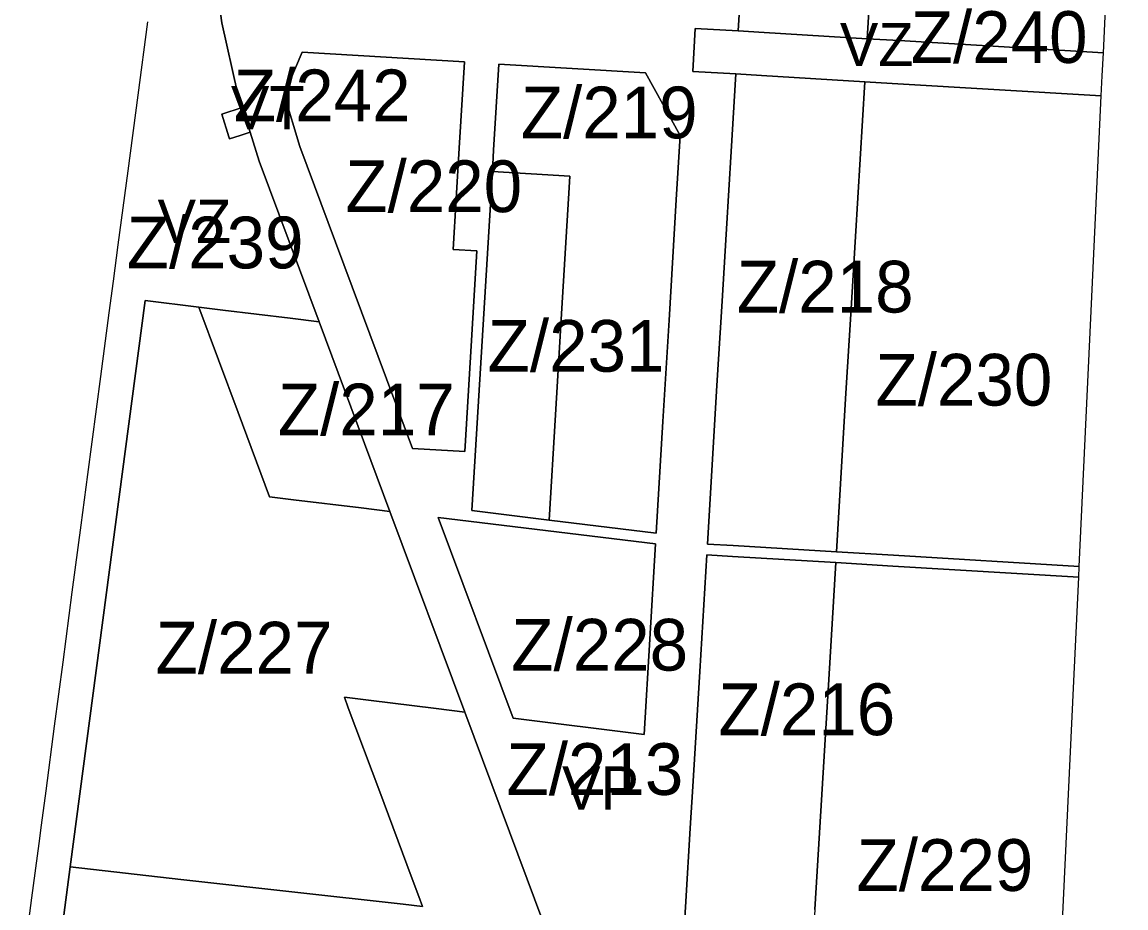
# Model space of a CAD drawing. Extents: x -521939 to -518034, y -1194984 to -1189555.
# Drawn here: x -519472.6 to -519216.4, y -1191421.3 to -1191215.8 of the extents above; entities that cross this region are included whole.
import ezdxf

# ---------------------------------------------------------------- set-up
doc = ezdxf.new("R2010")
doc.units = 0
for name, color, linetype in [('95420023', 7, 'Continuous'), ('96122023', 7, 'Continuous'), ('96202223', 7, 'Continuous'), ('96202323', 7, 'Continuous')]:
    doc.layers.add(name, color=color, linetype=linetype)

msp = doc.modelspace()

# ---------------------------------------------------------------- linework, layer by layer
at = {"layer": '95420023'}
for points in [[(-519269, -1191220.09), (-519221.65, -1191222.94), (-519219.11, -1191168.85), (-519216.44, -1191111.73), (-519216.41, -1191111.11)], [(-519302.94, -1191160.9), (-519304.09, -1191179.86), (-519305.23, -1191198.83), (-519306.37, -1191217.84)], [(-519306.37, -1191217.84), (-519305.23, -1191198.83), (-519304.09, -1191179.86), (-519302.94, -1191160.9)], [(-519274.14, -1191181.66), (-519275.28, -1191200.63), (-519276.43, -1191219.64)], [(-519276.43, -1191219.64), (-519275.28, -1191200.63), (-519274.14, -1191181.66)], [(-519428.47, -1191199.49), (-519426.21, -1191215.98)], [(-519426.21, -1191215.98), (-519428.47, -1191199.49)], [(-519443.51, -1191215.75), (-519445.75, -1191232.74), (-519448.07, -1191250.27), (-519450.34, -1191267.46), (-519451.46, -1191275.9), (-519452.43, -1191283.22), (-519454.38, -1191298), (-519457.39, -1191320.76), (-519458.94, -1191332.49), (-519461, -1191348.01), (-519463.15, -1191364.31), (-519465.11, -1191379.15), (-519467.09, -1191394.09), (-519468.15, -1191402.09), (-519468.71, -1191406.36), (-519470.37, -1191418.91), (-519472.32, -1191433.7), (-519472.58, -1191435.69)], [(-519426.21, -1191215.98), (-519422.56, -1191232.21)], [(-519422.56, -1191232.21), (-519426.21, -1191215.98)], [(-519316.35, -1191217.24), (-519316.95, -1191227.22), (-519306.97, -1191227.82)], [(-519316.95, -1191227.22), (-519316.35, -1191217.24)], [(-519306.37, -1191217.84), (-519316.35, -1191217.24)], [(-519316.35, -1191217.24), (-519306.37, -1191217.84)], [(-519276.43, -1191219.64), (-519300.38, -1191218.2), (-519306.37, -1191217.84)], [(-519306.37, -1191217.84), (-519300.38, -1191218.2), (-519276.43, -1191219.64)], [(-519221.65, -1191222.94), (-519269, -1191220.09), (-519276.43, -1191219.64)], [(-519276.43, -1191219.64), (-519269, -1191220.09)], [(-519371.12, -1191245), (-519369.92, -1191225.04), (-519407.56, -1191222.77), (-519411.75, -1191232.59)], [(-519411.75, -1191232.59), (-519407.56, -1191222.77), (-519369.92, -1191225.04), (-519371.12, -1191245)], [(-519270.66, -1191230.01), (-519222.12, -1191232.93), (-519221.9, -1191228.24), (-519221.65, -1191222.94)], [(-519361.93, -1191225.52), (-519363.14, -1191245.48), (-519363.44, -1191250.47)], [(-519363.44, -1191250.47), (-519363.14, -1191245.48), (-519361.93, -1191225.52)], [(-519327.89, -1191227.57), (-519361.93, -1191225.52)], [(-519361.93, -1191225.52), (-519327.89, -1191227.57)], [(-519319.85, -1191242.08), (-519327.89, -1191227.57)], [(-519327.89, -1191227.57), (-519319.85, -1191242.08)], [(-519310.22, -1191281.73), (-519309.14, -1191263.76), (-519308.05, -1191245.79), (-519306.97, -1191227.82), (-519316.95, -1191227.22)], [(-519306.97, -1191227.82), (-519308.05, -1191245.79), (-519309.14, -1191263.76)], [(-519300.98, -1191228.18), (-519306.97, -1191227.82)], [(-519306.97, -1191227.82), (-519300.98, -1191228.18), (-519277.03, -1191229.63)], [(-519277.03, -1191229.63), (-519300.98, -1191228.18)], [(-519278.11, -1191247.59), (-519277.03, -1191229.63)], [(-519277.03, -1191229.63), (-519278.11, -1191247.59)], [(-519270.66, -1191230.01), (-519277.03, -1191229.63)], [(-519277.03, -1191229.63), (-519270.66, -1191230.01)], [(-519227.23, -1191342.07), (-519227.23, -1191342.05), (-519224.53, -1191284.5), (-519222.12, -1191232.93), (-519270.66, -1191230.01)], [(-519422.56, -1191232.21), (-519421.48, -1191235.61)], [(-519421.48, -1191235.61), (-519422.56, -1191232.21)], [(-519411.75, -1191232.59), (-519408.14, -1191244.64)], [(-519408.14, -1191244.64), (-519411.75, -1191232.59)], [(-519424.44, -1191242.84), (-519424.56, -1191242.44), (-519426.25, -1191237.12), (-519421.48, -1191235.61)], [(-519421.48, -1191235.61), (-519426.25, -1191237.12)], [(-519421.48, -1191235.61), (-519421.46, -1191235.67)], [(-519421.46, -1191235.67), (-519421.48, -1191235.61)], [(-519421.46, -1191235.67), (-519420.1, -1191239.99)], [(-519420.1, -1191239.99), (-519421.46, -1191235.67)], [(-519426.25, -1191237.12), (-519424.56, -1191242.44)], [(-519419.67, -1191241.33), (-519421.98, -1191242.06), (-519424.44, -1191242.84)], [(-519421.98, -1191242.06), (-519419.67, -1191241.33)], [(-519420.1, -1191239.99), (-519419.67, -1191241.33)], [(-519419.67, -1191241.33), (-519420.1, -1191239.99)], [(-519419.67, -1191241.33), (-519417.54, -1191248.08), (-519403.63, -1191285.31), (-519387.2, -1191329.32)], [(-519417.54, -1191248.08), (-519419.67, -1191241.33)], [(-519424.56, -1191242.44), (-519424.44, -1191242.84)], [(-519424.44, -1191242.84), (-519421.98, -1191242.06)], [(-519322.43, -1191284.95), (-519320.75, -1191257), (-519319.85, -1191242.08)], [(-519319.85, -1191242.08), (-519320.75, -1191257)], [(-519408.14, -1191244.64), (-519399.84, -1191266.86), (-519381.99, -1191314.67)], [(-519381.99, -1191314.67), (-519399.84, -1191266.86), (-519408.14, -1191244.64)], [(-519372.54, -1191268.51), (-519371.12, -1191245)], [(-519371.12, -1191245), (-519372.54, -1191268.51)], [(-519403.63, -1191285.31), (-519417.54, -1191248.08)], [(-519283.59, -1191338.68), (-519282.48, -1191320.26), (-519281.38, -1191301.9), (-519280.27, -1191283.53), (-519279.19, -1191265.56), (-519278.11, -1191247.59)], [(-519278.11, -1191247.59), (-519279.19, -1191265.56)], [(-519363.44, -1191250.47), (-519368.17, -1191329.12)], [(-519368.17, -1191329.12), (-519363.44, -1191250.47)], [(-519363.44, -1191250.47), (-519354.45, -1191251.01), (-519345.47, -1191251.55)], [(-519354.45, -1191251.01), (-519363.44, -1191250.47)], [(-519345.47, -1191251.55), (-519354.45, -1191251.01)], [(-519347.39, -1191283.45), (-519345.71, -1191255.5), (-519345.47, -1191251.55)], [(-519345.47, -1191251.55), (-519345.71, -1191255.5)], [(-519345.71, -1191255.5), (-519347.39, -1191283.45), (-519348.8, -1191306.9)], [(-519320.75, -1191257), (-519322.43, -1191284.95)], [(-519309.14, -1191263.76), (-519310.22, -1191281.73)], [(-519279.19, -1191265.56), (-519280.27, -1191283.53)], [(-519368.53, -1191293.54), (-519367.05, -1191268.84), (-519372.54, -1191268.51)], [(-519372.54, -1191268.51), (-519367.05, -1191268.84)], [(-519367.05, -1191268.84), (-519368.53, -1191293.54)], [(-519444.02, -1191280.38), (-519461.41, -1191411.78)], [(-519461.41, -1191411.78), (-519444.02, -1191280.38), (-519431.59, -1191281.9)], [(-519431.59, -1191281.9), (-519444.02, -1191280.38)], [(-519410.34, -1191284.49), (-519426, -1191282.58), (-519431.59, -1191281.9)], [(-519431.59, -1191281.9), (-519422.47, -1191306.33)], [(-519422.47, -1191306.33), (-519431.59, -1191281.9)], [(-519431.59, -1191281.9), (-519426, -1191282.58)], [(-519426, -1191282.58), (-519410.34, -1191284.49)], [(-519310.22, -1191281.73), (-519311.32, -1191300.09)], [(-519311.32, -1191300.09), (-519310.22, -1191281.73)], [(-519403.63, -1191285.31), (-519410.34, -1191284.49)], [(-519410.34, -1191284.49), (-519403.63, -1191285.31)], [(-519368.17, -1191329.12), (-519350.27, -1191331.3), (-519348.8, -1191306.9), (-519347.39, -1191283.45)], [(-519323.85, -1191308.41), (-519322.43, -1191284.95)], [(-519322.43, -1191284.95), (-519323.85, -1191308.41)], [(-519280.27, -1191283.53), (-519281.38, -1191301.9)], [(-519387.2, -1191329.32), (-519403.63, -1191285.31)], [(-519369.85, -1191315.4), (-519368.53, -1191293.54)], [(-519368.53, -1191293.54), (-519369.85, -1191315.4)], [(-519311.32, -1191300.09), (-519312.43, -1191318.46), (-519313.54, -1191336.88), (-519307.55, -1191337.24), (-519283.59, -1191338.68)], [(-519312.43, -1191318.46), (-519311.32, -1191300.09)], [(-519281.38, -1191301.9), (-519282.48, -1191320.26), (-519283.59, -1191338.68)], [(-519422.47, -1191306.33), (-519415.16, -1191325.91), (-519409.56, -1191326.59), (-519393.91, -1191328.5)], [(-519415.16, -1191325.91), (-519422.47, -1191306.33)], [(-519348.8, -1191306.9), (-519350.27, -1191331.3)], [(-519325.41, -1191334.34), (-519323.85, -1191308.41)], [(-519323.85, -1191308.41), (-519325.41, -1191334.34)], [(-519381.99, -1191314.67), (-519369.85, -1191315.4)], [(-519369.85, -1191315.4), (-519381.99, -1191314.67)], [(-519283.59, -1191338.68), (-519307.55, -1191337.24), (-519313.54, -1191336.88), (-519312.43, -1191318.46)], [(-519409.56, -1191326.59), (-519415.16, -1191325.91)], [(-519393.91, -1191328.5), (-519409.56, -1191326.59)], [(-519393.91, -1191328.5), (-519387.2, -1191329.32)], [(-519387.2, -1191329.32), (-519393.91, -1191328.5)], [(-519369.81, -1191375.88), (-519387.2, -1191329.32)], [(-519387.2, -1191329.32), (-519369.81, -1191375.88)], [(-519325.56, -1191336.84), (-519376.01, -1191330.68)], [(-519376.01, -1191330.68), (-519358.62, -1191377.27), (-519328.22, -1191381.04)], [(-519358.62, -1191377.27), (-519376.01, -1191330.68), (-519325.56, -1191336.84)], [(-519350.27, -1191331.3), (-519368.17, -1191329.12)], [(-519350.27, -1191331.3), (-519325.41, -1191334.34)], [(-519325.41, -1191334.34), (-519350.27, -1191331.3)], [(-519328.22, -1191381.04), (-519325.56, -1191336.84)], [(-519325.56, -1191336.84), (-519328.22, -1191381.04)], [(-519283.59, -1191338.68), (-519270.38, -1191339.47)], [(-519270.38, -1191339.47), (-519283.59, -1191338.68)], [(-519313.69, -1191339.37), (-519315.32, -1191366.47), (-519316.93, -1191393.15), (-519317.5, -1191402.75), (-519318.53, -1191419.83), (-519320.06, -1191445.13), (-519320.82, -1191457.76)], [(-519317.5, -1191402.75), (-519316.93, -1191393.15), (-519315.32, -1191366.47), (-519313.69, -1191339.37)], [(-519307.7, -1191339.73), (-519313.69, -1191339.37)], [(-519313.69, -1191339.37), (-519307.7, -1191339.73)], [(-519283.74, -1191341.17), (-519307.7, -1191339.73)], [(-519307.7, -1191339.73), (-519283.74, -1191341.17)], [(-519283.74, -1191341.17), (-519285.37, -1191368.28)], [(-519285.37, -1191368.28), (-519283.74, -1191341.17)], [(-519270.52, -1191341.97), (-519283.74, -1191341.17)], [(-519283.74, -1191341.17), (-519270.52, -1191341.97)], [(-519270.38, -1191339.47), (-519227.23, -1191342.07)], [(-519227.23, -1191342.07), (-519270.38, -1191339.47)], [(-519233.5, -1191475.79), (-519231.17, -1191426.05), (-519228.55, -1191370.34), (-519227.35, -1191344.57), (-519270.52, -1191341.97)], [(-519270.52, -1191341.97), (-519227.35, -1191344.57), (-519227.23, -1191342.07)], [(-519285.37, -1191368.28), (-519286.98, -1191394.95)], [(-519286.98, -1191394.95), (-519285.37, -1191368.28)], [(-519382.3, -1191413.9), (-519389.59, -1191394.38), (-519396.88, -1191374.85), (-519397.79, -1191372.41)], [(-519397.79, -1191372.41), (-519392.19, -1191373.11)], [(-519392.19, -1191373.11), (-519397.79, -1191372.41)], [(-519397.79, -1191372.41), (-519396.88, -1191374.85), (-519389.59, -1191394.38), (-519382.3, -1191413.9)], [(-519392.19, -1191373.11), (-519376.52, -1191375.05)], [(-519376.52, -1191375.05), (-519392.19, -1191373.11)], [(-519376.52, -1191375.05), (-519369.81, -1191375.88)], [(-519369.81, -1191375.88), (-519376.52, -1191375.05)], [(-519344.11, -1191444.69), (-519355.34, -1191414.63), (-519369.81, -1191375.88)], [(-519369.81, -1191375.88), (-519355.34, -1191414.63)], [(-519328.22, -1191381.04), (-519358.62, -1191377.27)], [(-519286.98, -1191394.95), (-519288.59, -1191421.63), (-519290.11, -1191446.93)], [(-519288.59, -1191421.63), (-519286.98, -1191394.95)], [(-519320.82, -1191457.76), (-519320.06, -1191445.13), (-519318.53, -1191419.83), (-519317.5, -1191402.75)], [(-519410, -1191417.54), (-519435.74, -1191414.66), (-519461.41, -1191411.78), (-519463.91, -1191430.62)], [(-519463.91, -1191430.62), (-519461.41, -1191411.78)], [(-519461.41, -1191411.78), (-519435.74, -1191414.66), (-519410, -1191417.54), (-519384.16, -1191420.43), (-519379.67, -1191420.94)], [(-519355.34, -1191414.63), (-519344.11, -1191444.69), (-519347.98, -1191449.64), (-519386.94, -1191445.28), (-519412.78, -1191442.38)], [(-519380.54, -1191418.61), (-519382.3, -1191413.9)], [(-519382.3, -1191413.9), (-519380.54, -1191418.61)], [(-519384.16, -1191420.43), (-519410, -1191417.54)], [(-519379.67, -1191420.94), (-519384.16, -1191420.43)], [(-519379.67, -1191420.94), (-519380.54, -1191418.61)], [(-519380.54, -1191418.61), (-519379.67, -1191420.94)]]:
    msp.add_lwpolyline(points, dxfattribs=at)
at = {"layer": '96122023'}
for points in [[(-519421.48, -1191235.61), (-519426.25, -1191237.12)], [(-519421.46, -1191235.67), (-519421.48, -1191235.61)], [(-519420.1, -1191239.99), (-519421.46, -1191235.67)], [(-519426.25, -1191237.12), (-519424.56, -1191242.44)], [(-519421.98, -1191242.06), (-519419.67, -1191241.33)], [(-519419.67, -1191241.33), (-519420.1, -1191239.99)], [(-519424.56, -1191242.44), (-519424.44, -1191242.84)], [(-519424.44, -1191242.84), (-519421.98, -1191242.06)]]:
    msp.add_lwpolyline(points, dxfattribs=at)
at = {"layer": '96202223'}
for points in [[(-519426.21, -1191215.98), (-519428.47, -1191199.49)], [(-519443.51, -1191215.75), (-519445.75, -1191232.74), (-519448.07, -1191250.27), (-519450.34, -1191267.46), (-519451.46, -1191275.9), (-519452.43, -1191283.22), (-519454.38, -1191298), (-519457.39, -1191320.76), (-519458.94, -1191332.49), (-519461, -1191348.01), (-519463.15, -1191364.31), (-519465.11, -1191379.15), (-519467.09, -1191394.09), (-519468.15, -1191402.09), (-519468.71, -1191406.36), (-519470.37, -1191418.91), (-519472.32, -1191433.7), (-519472.58, -1191435.69)], [(-519422.56, -1191232.21), (-519426.21, -1191215.98)], [(-519316.35, -1191217.24), (-519316.95, -1191227.22)], [(-519306.37, -1191217.84), (-519316.35, -1191217.24)], [(-519276.43, -1191219.64), (-519300.38, -1191218.2), (-519306.37, -1191217.84)], [(-519269, -1191220.09), (-519276.43, -1191219.64)], [(-519221.65, -1191222.94), (-519269, -1191220.09)], [(-519270.66, -1191230.01), (-519222.12, -1191232.93), (-519221.9, -1191228.24), (-519221.65, -1191222.94)], [(-519316.95, -1191227.22), (-519306.97, -1191227.82)], [(-519306.97, -1191227.82), (-519300.98, -1191228.18), (-519277.03, -1191229.63)], [(-519277.03, -1191229.63), (-519270.66, -1191230.01)], [(-519421.48, -1191235.61), (-519422.56, -1191232.21)], [(-519426.25, -1191237.12), (-519421.48, -1191235.61)], [(-519424.56, -1191242.44), (-519426.25, -1191237.12)], [(-519419.67, -1191241.33), (-519421.98, -1191242.06)], [(-519417.54, -1191248.08), (-519419.67, -1191241.33)], [(-519424.44, -1191242.84), (-519424.56, -1191242.44)], [(-519421.98, -1191242.06), (-519424.44, -1191242.84)], [(-519403.63, -1191285.31), (-519417.54, -1191248.08)], [(-519461.41, -1191411.78), (-519444.02, -1191280.38)], [(-519444.02, -1191280.38), (-519431.59, -1191281.9)], [(-519431.59, -1191281.9), (-519426, -1191282.58)], [(-519426, -1191282.58), (-519410.34, -1191284.49)], [(-519410.34, -1191284.49), (-519403.63, -1191285.31)], [(-519463.91, -1191430.62), (-519461.41, -1191411.78)]]:
    msp.add_lwpolyline(points, dxfattribs=at)
at = {"layer": '96202323'}
for points in [[(-519306.37, -1191217.84), (-519305.23, -1191198.83), (-519304.09, -1191179.86)], [(-519428.47, -1191199.49), (-519426.21, -1191215.98)], [(-519426.21, -1191215.98), (-519422.56, -1191232.21)], [(-519316.95, -1191227.22), (-519316.35, -1191217.24)], [(-519316.35, -1191217.24), (-519306.37, -1191217.84)], [(-519411.75, -1191232.59), (-519407.56, -1191222.77), (-519369.92, -1191225.04)], [(-519369.92, -1191225.04), (-519371.12, -1191245)], [(-519363.44, -1191250.47), (-519363.14, -1191245.48), (-519361.93, -1191225.52)], [(-519361.93, -1191225.52), (-519327.89, -1191227.57)], [(-519327.89, -1191227.57), (-519319.85, -1191242.08)], [(-519306.97, -1191227.82), (-519316.95, -1191227.22)], [(-519308.05, -1191245.79), (-519306.97, -1191227.82)], [(-519422.56, -1191232.21), (-519421.48, -1191235.61)], [(-519408.14, -1191244.64), (-519411.75, -1191232.59)], [(-519421.48, -1191235.61), (-519421.46, -1191235.67)], [(-519421.46, -1191235.67), (-519420.1, -1191239.99)], [(-519420.1, -1191239.99), (-519419.67, -1191241.33)], [(-519419.67, -1191241.33), (-519417.54, -1191248.08), (-519403.63, -1191285.31), (-519387.2, -1191329.32)], [(-519319.85, -1191242.08), (-519320.75, -1191257)], [(-519381.99, -1191314.67), (-519399.84, -1191266.86), (-519408.14, -1191244.64)], [(-519371.12, -1191245), (-519372.54, -1191268.51)], [(-519310.22, -1191281.73), (-519309.14, -1191263.76), (-519308.05, -1191245.79)], [(-519368.17, -1191329.12), (-519363.44, -1191250.47)], [(-519320.75, -1191257), (-519322.43, -1191284.95)], [(-519372.54, -1191268.51), (-519367.05, -1191268.84)], [(-519367.05, -1191268.84), (-519368.53, -1191293.54)], [(-519311.32, -1191300.09), (-519310.22, -1191281.73)], [(-519322.43, -1191284.95), (-519323.85, -1191308.41)], [(-519368.53, -1191293.54), (-519369.85, -1191315.4)], [(-519283.59, -1191338.68), (-519307.55, -1191337.24), (-519313.54, -1191336.88), (-519312.43, -1191318.46), (-519311.32, -1191300.09)], [(-519323.85, -1191308.41), (-519325.41, -1191334.34)], [(-519369.85, -1191315.4), (-519381.99, -1191314.67)], [(-519387.2, -1191329.32), (-519369.81, -1191375.88)], [(-519358.62, -1191377.27), (-519376.01, -1191330.68)], [(-519376.01, -1191330.68), (-519325.56, -1191336.84)], [(-519350.27, -1191331.3), (-519368.17, -1191329.12)], [(-519325.41, -1191334.34), (-519350.27, -1191331.3)], [(-519325.56, -1191336.84), (-519328.22, -1191381.04)], [(-519270.38, -1191339.47), (-519283.59, -1191338.68)], [(-519315.32, -1191366.47), (-519313.69, -1191339.37)], [(-519313.69, -1191339.37), (-519307.7, -1191339.73)], [(-519307.7, -1191339.73), (-519283.74, -1191341.17)], [(-519283.74, -1191341.17), (-519270.52, -1191341.97)], [(-519227.23, -1191342.07), (-519270.38, -1191339.47)], [(-519270.52, -1191341.97), (-519227.35, -1191344.57), (-519227.23, -1191342.07)], [(-519316.93, -1191393.15), (-519315.32, -1191366.47)], [(-519369.81, -1191375.88), (-519355.34, -1191414.63)], [(-519328.22, -1191381.04), (-519358.62, -1191377.27)], [(-519318.53, -1191419.83), (-519317.5, -1191402.75), (-519316.93, -1191393.15)], [(-519355.34, -1191414.63), (-519344.11, -1191444.69)], [(-519320.82, -1191457.76), (-519320.06, -1191445.13), (-519318.53, -1191419.83)]]:
    msp.add_lwpolyline(points, dxfattribs=at)

# ---------------------------------------------------------------- texts
at = {"layer": '95420023'}
for s, rotation, p in [('Z/240', 360, (-519266.35, -1191225.26)), ('Z/242', 0, (-519423.45, -1191238.79)), ('Z/219', 360, (-519356.83, -1191242.75)), ('Z/220', 360, (-519397.56, -1191259.87)), ('Z/239', 360, (-519448.3, -1191272.92)), ('Z/218', 0, (-519306.72, -1191283.16)), ('Z/231', 360, (-519364.54, -1191296.9)), ('Z/230', 360, (-519274.53, -1191304.75)), ('Z/217', 0, (-519413.22, -1191311.66)), ('Z/227', 0, (-519441.59, -1191366.91)), ('Z/228', 360, (-519359.05, -1191366.23)), ('Z/216', 0, (-519310.98, -1191381.21)), ('Z/213', 0, (-519360.16, -1191395.07)), ('Z/229', 0, (-519278.93, -1191417.34))]:
    msp.add_text(s, height=12, rotation=rotation, dxfattribs=at).set_placement(p)
at = {"layer": '96122023'}
msp.add_text('VT', height=10, rotation=0, dxfattribs=at).set_placement((-519424.11, -1191240.64))
at = {"layer": '96202223'}
msp.add_text('VZ', height=10, rotation=0, dxfattribs=at).set_placement((-519282.79, -1191226))
msp.add_text('VZ', height=10, dxfattribs=at).set_placement((-519441.13, -1191267.01))
at = {"layer": '96202323'}
msp.add_text('VP', height=10, rotation=360, dxfattribs=at).set_placement((-519347.26, -1191398.47))

doc.saveas('drawing.dxf')
